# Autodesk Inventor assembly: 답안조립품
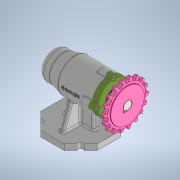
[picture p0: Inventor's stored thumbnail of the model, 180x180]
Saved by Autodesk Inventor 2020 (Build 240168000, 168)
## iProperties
Created: 2021-01
Part Number: 답안조립품
Document SubType Name: Assembly
Designer: PC2-08
Author: PC2-08
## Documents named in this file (12)
- C:\Users\PC2-08\Desktop\710106V1025\답안조립품.iam
- C:\Users\PC2-08\Desktop\710106V1025\본체.ipt
- C:\Users\PC2-08\Desktop\710106V1025\베어링 6004.ipt
- C:\Users\PC2-08\Desktop\710106V1025\커버.ipt
- C:\Users\PC2-08\Desktop\710106V1025\축.ipt
- C:\Users\PC2-08\Desktop\710106V1025\오일 실.ipt
- C:\Users\PC2-08\Desktop\710106V1025\키 5 x 5 x 14.ipt
- C:\Users\PC2-08\Desktop\710106V1025\어댑터슬리브.ipt
- C:\Users\PC2-08\Desktop\710106V1025\베어링 51202.ipt
- C:\Users\PC2-08\Desktop\710106V1025\볼트 M4.ipt
- C:\Users\PC2-08\Desktop\710106V1025\스프로킷.ipt
- C:\Users\PC2-08\Desktop\710106V1025\멈춤나사 M3.ipt
